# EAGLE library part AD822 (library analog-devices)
Single-Supply, Rail-to-Rail Low Power FET-Input Op Amp Source: http://www.analog.com/static/imported-files/data_sheets/AD822.pdf
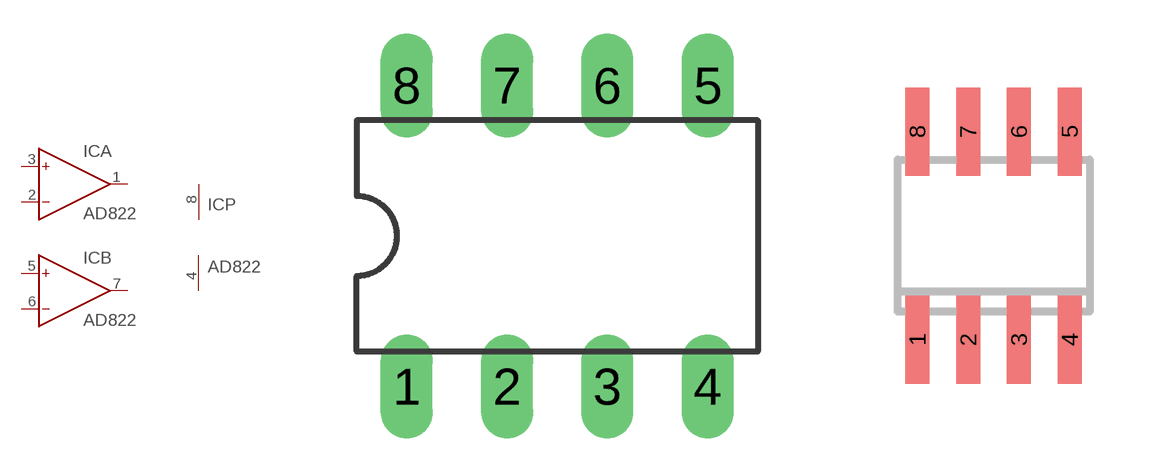
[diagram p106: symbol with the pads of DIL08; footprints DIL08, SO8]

Designator prefix IC; gates A=OP B=OP P=PWR+-

## AD822N (OC_FARNELL: 1438581; OC_NEWARK: unknown)  [DIL08]
1  A:OUT  out
2  A:IN-  in
3  A:IN+  in
4  P:V-  pwr
5  B:IN+  in
6  B:IN-  in
7  B:OUT  out
8  P:V+  pwr

## AD822R (MF: ANALOG DEVICES; MPN: AD822BRZ; OC_FARNELL: 1651303)  [SO8]
Pads as for DIL08

## AD822RM (MPN: AD822ARMZ-R2; OC_FARNELL: 1827360; OC_NEWARK: 19M8890)  [MSOP08]
Pads as for DIL08

## Footprint DIL08 (pad centres in mm)
Dual In Line Package
drill 0.813 long: 1 -3.81,-3.81; 2 -1.27,-3.81; 3 1.27,-3.81; 4 3.81,-3.81; 5 3.81,3.81; 6 1.27,3.81; 7 -1.27,3.81; 8 -3.81,3.81

## Footprint SO8 (pad centres in mm)
8-Lead Small Outline IC (SO-8) Source: http://www.analog.com/UploadedFiles/Data_Sheets/703465986AD8611_2_0.pdf
smd 0.6 x 2.2: 1 -1.905,-2.6; 2 -0.635,-2.6; 3 0.635,-2.6; 4 1.905,-2.6; 5 1.905,2.6; 6 0.635,2.6; 7 -0.635,2.6; 8 -1.905,2.6

## Footprint MSOP08 (pad centres in mm)
8-Lead micro SO (RM-8) Source: http://www.analog.com/UploadedFiles/Data_Sheets/703465986AD8611_2_0.pdf
smd 0.4 x 1: 1 -0.976,-2.263; 2 -0.326,-2.263; 3 0.324,-2.263; 4 0.974,-2.263; 5 0.974,2.262; 6 0.324,2.262; 7 -0.326,2.262; 8 -0.976,2.262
